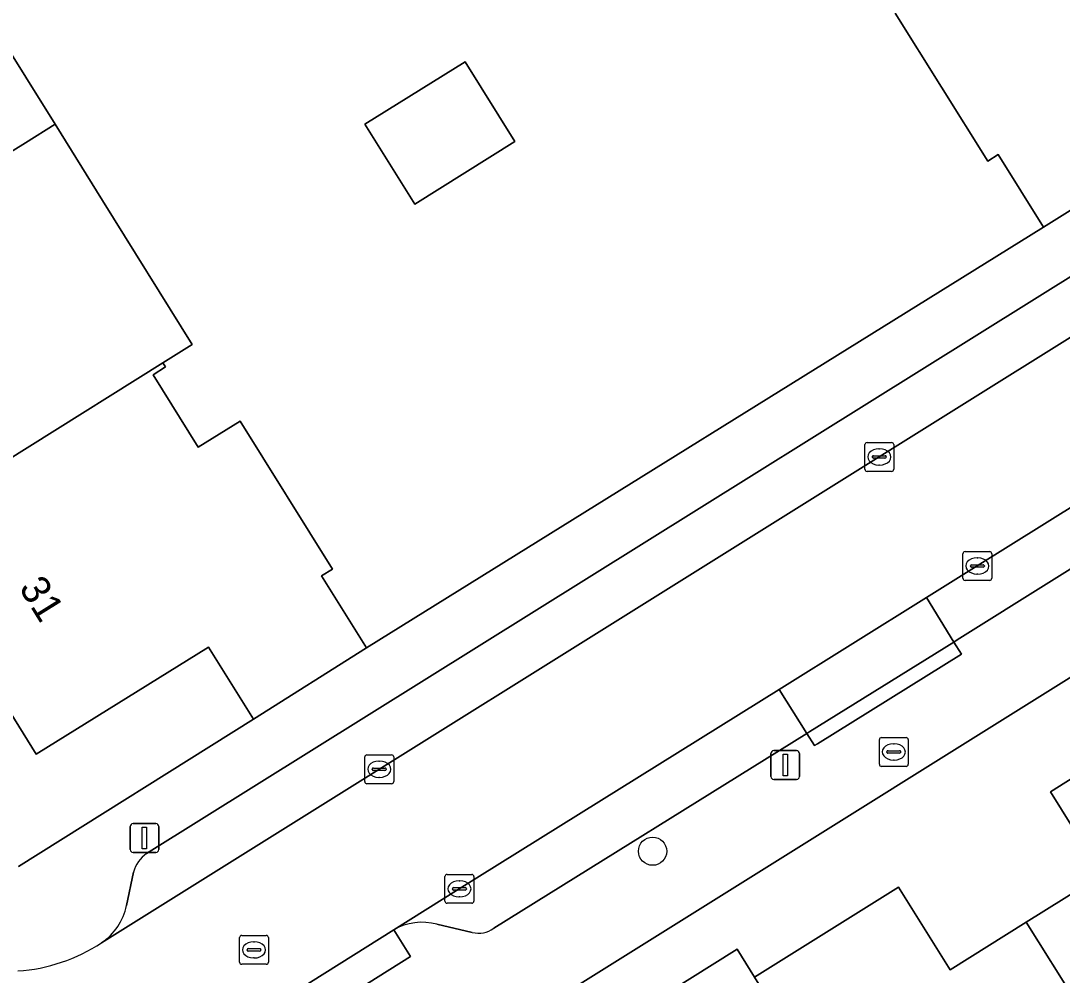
# Model space of a CAD drawing. Extents: x 158835 to 160077, y 386387 to 387778.
# Drawn here: x 159128.32 to 159164.41, y 386936.5 to 386969.57 of the extents above; entities that cross this region are included whole.
import ezdxf

# ---------------------------------------------------------------- set-up
doc = ezdxf.new("R2010")
doc.units = 0
for name, color, linetype in [('IMGEO_Boom', 7, 'Continuous'), ('IMGEO_Brandkraan', 7, 'Continuous'), ('IMGEO_Erf', 7, 'Continuous'), ('IMGEO_Kolk', 7, 'Continuous'), ('IMGEO_Lichtmast', 7, 'Continuous'), ('IMGEO_Muur', 7, 'Continuous'), ('IMGEO_Pand', 7, 'Continuous'), ('IMGEO_Pand_nummerreeks', 7, 'Continuous'), ('IMGEO_Parkeervlak_open', 7, 'Continuous'), ('IMGEO_Rijbaan_lokaal_gesloten', 7, 'Continuous'), ('IMGEO_Rioolput', 7, 'Continuous'), ('IMGEO_Voetpad_open', 7, 'Continuous')]:
    doc.layers.add(name, color=color, linetype=linetype)

msp = doc.modelspace()

# ---------------------------------------------------------------- linework, layer by layer
at = {"layer": 'IMGEO_Boom'}
msp.add_circle((159150.211, 386940.794), 0.489, dxfattribs=at)
at = {"layer": 'IMGEO_Brandkraan'}
for p, q in [((159158.07, 386943.808), (159158.07, 386944.66)), ((159158.145, 386944.734), (159158.997, 386944.734)), ((159158.558, 386944.514), (159158.583, 386944.514)), ((159159.071, 386944.66), (159159.071, 386943.808)), ((159158.329, 386944.228), (159158.329, 386944.24)), ((159158.767, 386944.191), (159158.369, 386944.191)), ((159158.372, 386944.277), (159158.77, 386944.277)), ((159158.813, 386944.24), (159158.813, 386944.228)), ((159158.997, 386943.734), (159158.145, 386943.734)), ((159158.581, 386943.954), (159158.556, 386943.954))]:
    msp.add_line(p, q, dxfattribs=at)
for points in [[(159158.07, 386943.808), (159158.07, 386944.66)], [(159158.145, 386944.734), (159158.997, 386944.734)], [(159159.071, 386944.66), (159159.071, 386943.808)], [(159158.997, 386943.734), (159158.145, 386943.734)]]:
    msp.add_lwpolyline(points, dxfattribs=at)
for centre, radius, start, end in [((159158.147, 386944.658), 0.0765, 91.552, 178.448), ((159158.147, 386944.658), 0.0765, 91.552, 178.448), ((159158.995, 386944.658), 0.0765, 1.552, 88.448), ((159158.995, 386944.658), 0.0765, 1.552, 88.448), ((159158.369, 386944.237), 0.0403, 85.8775, 175.7526), ((159158.366, 386944.227), 0.0366, 178.938, 274.7102), ((159158.77, 386944.234), 0.043, 264.8664, 352.4533), ((159158.774, 386944.239), 0.0386, 1.7309, 96.639), ((159158.147, 386943.81), 0.0765, 181.552, 268.448), ((159158.147, 386943.81), 0.0765, 181.552, 268.448), ((159158.995, 386943.81), 0.0765, 271.552, 358.448), ((159158.995, 386943.81), 0.0765, 271.552, 358.448)]:
    msp.add_arc(centre, radius, start, end, dxfattribs=at)
for centre, major_axis, ratio, start_param, end_param in [((159158.557, 386944.234), (-0.387, 0.002), 0.722429, 4.712389, 7.853982), ((159158.582, 386944.234), (-0.39, 0.002), 0.717154, 1.570796, 4.712389)]:
    msp.add_ellipse(centre, major_axis=major_axis, ratio=ratio, start_param=start_param, end_param=end_param, dxfattribs=at)
at = {"layer": 'IMGEO_Erf'}
for points in [[(159218.693, 386980.571), (159146.59, 386935.503)], [(159126.388, 386970.975), (159129.502, 386965.983), (159131.152, 386963.338), (159134.261, 386958.353), (159133.243, 386957.719), (159133.333, 386957.575), (159132.901, 386957.305), (159134.466, 386954.796), (159135.915, 386955.7), (159139.114, 386950.571), (159138.741, 386950.339), (159140.301, 386947.838), (159163.761, 386962.422), (159162.19, 386964.939), (159161.825, 386964.711), (159158.624, 386969.839)], [(159149.953, 386935.401), (159153.141, 386937.398), (159153.743, 386936.431), (159158.73, 386939.548), (159160.521, 386936.682), (159163.157, 386938.33), (159165.794, 386939.978), (159163.997, 386942.852), (159165.82, 386943.991), (159165.221, 386944.949), (159168.408, 386946.941), (159169.005, 386945.982), (159174, 386949.104), (159175.791, 386946.239), (159178.419, 386947.882), (159181.056, 386949.53), (159179.265, 386952.395), (159184.255, 386955.514), (159183.658, 386956.474), (159186.829, 386958.456), (159187.428, 386957.498), (159189.234, 386958.626), (159191.03, 386955.753), (159193.667, 386957.401)], [(159128.234, 386940.266), (159136.383, 386945.364), (159134.825, 386947.869), (159128.849, 386944.162), (159125.646, 386949.307)]]:
    msp.add_lwpolyline(points, dxfattribs=at)
msp.add_lwpolyline([(159140.242, 386965.987), (159143.715, 386968.153), (159145.443, 386965.383), (159141.97, 386963.217)], close=True, dxfattribs=at)
at = {"layer": 'IMGEO_Kolk'}
for p, q in [((159157.643, 386954.956), (159158.495, 386954.956)), ((159157.568, 386954.03), (159157.568, 386954.882)), ((159158.056, 386954.736), (159158.081, 386954.736)), ((159158.569, 386954.882), (159158.569, 386954.03)), ((159157.827, 386954.45), (159157.827, 386954.462)), ((159158.265, 386954.413), (159157.867, 386954.413)), ((159157.87, 386954.499), (159158.268, 386954.499)), ((159158.311, 386954.462), (159158.311, 386954.45)), ((159158.495, 386953.956), (159157.643, 386953.956)), ((159158.079, 386954.176), (159158.054, 386954.176)), ((159160.967, 386950.251), (159160.967, 386951.103)), ((159161.042, 386951.177), (159161.894, 386951.177)), ((159161.455, 386950.957), (159161.48, 386950.957)), ((159161.968, 386951.103), (159161.968, 386950.251)), ((159161.226, 386950.671), (159161.226, 386950.683)), ((159161.664, 386950.634), (159161.266, 386950.634)), ((159161.269, 386950.72), (159161.667, 386950.72)), ((159161.71, 386950.683), (159161.71, 386950.671)), ((159161.478, 386950.397), (159161.453, 386950.397)), ((159161.894, 386950.177), (159161.042, 386950.177)), ((159140.313, 386944.133), (159141.165, 386944.133)), ((159140.238, 386943.207), (159140.238, 386944.059)), ((159140.726, 386943.913), (159140.751, 386943.913)), ((159141.239, 386944.059), (159141.239, 386943.207)), ((159140.497, 386943.627), (159140.497, 386943.639)), ((159140.935, 386943.59), (159140.537, 386943.59)), ((159140.54, 386943.676), (159140.938, 386943.676)), ((159140.981, 386943.639), (159140.981, 386943.627)), ((159141.165, 386943.133), (159140.313, 386943.133)), ((159140.749, 386943.353), (159140.724, 386943.353)), ((159143.017, 386939.064), (159143.017, 386939.916)), ((159143.092, 386939.99), (159143.944, 386939.99)), ((159143.505, 386939.77), (159143.53, 386939.77)), ((159144.018, 386939.916), (159144.018, 386939.064)), ((159143.276, 386939.484), (159143.276, 386939.496)), ((159143.714, 386939.447), (159143.316, 386939.447)), ((159143.319, 386939.533), (159143.717, 386939.533)), ((159143.76, 386939.496), (159143.76, 386939.484)), ((159143.528, 386939.21), (159143.503, 386939.21)), ((159143.944, 386938.99), (159143.092, 386938.99))]:
    msp.add_line(p, q, dxfattribs=at)
for points in [[(159157.643, 386954.956), (159158.495, 386954.956)], [(159157.568, 386954.03), (159157.568, 386954.882)], [(159158.569, 386954.882), (159158.569, 386954.03)], [(159158.495, 386953.956), (159157.643, 386953.956)], [(159160.967, 386950.251), (159160.967, 386951.103)], [(159161.042, 386951.177), (159161.894, 386951.177)], [(159161.968, 386951.103), (159161.968, 386950.251)], [(159161.894, 386950.177), (159161.042, 386950.177)], [(159140.313, 386944.133), (159141.165, 386944.133)], [(159140.238, 386943.207), (159140.238, 386944.059)], [(159141.239, 386944.059), (159141.239, 386943.207)], [(159141.165, 386943.133), (159140.313, 386943.133)], [(159143.017, 386939.064), (159143.017, 386939.916)], [(159143.092, 386939.99), (159143.944, 386939.99)], [(159144.018, 386939.916), (159144.018, 386939.064)], [(159143.944, 386938.99), (159143.092, 386938.99)]]:
    msp.add_lwpolyline(points, dxfattribs=at)
for centre, radius, start, end in [((159157.645, 386954.88), 0.0765, 91.552, 178.448), ((159157.645, 386954.88), 0.0765, 91.552, 178.448), ((159158.493, 386954.88), 0.0765, 1.552, 88.448), ((159158.493, 386954.88), 0.0765, 1.552, 88.448), ((159157.867, 386954.459), 0.0403, 85.8775, 175.7526), ((159157.864, 386954.449), 0.0366, 178.938, 274.7102), ((159158.268, 386954.456), 0.043, 264.8664, 352.4533), ((159158.272, 386954.461), 0.0386, 1.7309, 96.639), ((159157.645, 386954.032), 0.0765, 181.552, 268.448), ((159157.645, 386954.032), 0.0765, 181.552, 268.448), ((159158.493, 386954.032), 0.0765, 271.552, 358.448), ((159158.493, 386954.032), 0.0765, 271.552, 358.448), ((159161.044, 386951.101), 0.0765, 91.552, 178.448), ((159161.044, 386951.101), 0.0765, 91.552, 178.448), ((159161.892, 386951.101), 0.0765, 1.552, 88.448), ((159161.892, 386951.101), 0.0765, 1.552, 88.448), ((159161.266, 386950.68), 0.0403, 85.8775, 175.7526), ((159161.263, 386950.67), 0.0366, 178.938, 274.7102), ((159161.667, 386950.677), 0.043, 264.8664, 352.4533), ((159161.671, 386950.682), 0.0386, 1.7309, 96.639), ((159161.044, 386950.253), 0.0765, 181.552, 268.448), ((159161.044, 386950.253), 0.0765, 181.552, 268.448), ((159161.892, 386950.253), 0.0765, 271.552, 358.448), ((159161.892, 386950.253), 0.0765, 271.552, 358.448), ((159140.315, 386944.057), 0.0765, 91.552, 178.448), ((159140.315, 386944.057), 0.0765, 91.552, 178.448), ((159141.163, 386944.057), 0.0765, 1.552, 88.448), ((159141.163, 386944.057), 0.0765, 1.552, 88.448), ((159140.537, 386943.636), 0.0403, 85.8775, 175.7526), ((159140.534, 386943.626), 0.0366, 178.938, 274.7102), ((159140.938, 386943.633), 0.043, 264.8664, 352.4533), ((159140.942, 386943.638), 0.0386, 1.7309, 96.639), ((159140.315, 386943.209), 0.0765, 181.552, 268.448), ((159140.315, 386943.209), 0.0765, 181.552, 268.448), ((159141.163, 386943.209), 0.0765, 271.552, 358.448), ((159141.163, 386943.209), 0.0765, 271.552, 358.448), ((159143.094, 386939.914), 0.0765, 91.552, 178.448), ((159143.094, 386939.914), 0.0765, 91.552, 178.448), ((159143.942, 386939.914), 0.0765, 1.552, 88.448), ((159143.942, 386939.914), 0.0765, 1.552, 88.448), ((159143.316, 386939.493), 0.0403, 85.8775, 175.7526), ((159143.313, 386939.483), 0.0366, 178.938, 274.7102), ((159143.717, 386939.49), 0.043, 264.8664, 352.4533), ((159143.721, 386939.495), 0.0386, 1.7309, 96.639), ((159143.094, 386939.066), 0.0765, 181.552, 268.448), ((159143.094, 386939.066), 0.0765, 181.552, 268.448), ((159143.942, 386939.066), 0.0765, 271.552, 358.448), ((159143.942, 386939.066), 0.0765, 271.552, 358.448)]:
    msp.add_arc(centre, radius, start, end, dxfattribs=at)
for centre, major_axis, ratio, start_param, end_param in [((159158.055, 386954.456), (-0.387, 0.002), 0.722429, 4.712389, 7.853982), ((159158.08, 386954.456), (-0.39, 0.002), 0.717154, 1.570796, 4.712389), ((159161.454, 386950.677), (-0.387, 0.002), 0.722429, 4.712389, 7.853982), ((159161.479, 386950.677), (-0.39, 0.002), 0.717154, 1.570796, 4.712389), ((159140.725, 386943.633), (-0.387, 0.002), 0.722429, 4.712389, 7.853982), ((159140.75, 386943.633), (-0.39, 0.002), 0.717154, 1.570796, 4.712389), ((159143.504, 386939.49), (-0.387, 0.002), 0.722429, 4.712389, 7.853982), ((159143.529, 386939.49), (-0.39, 0.002), 0.717154, 1.570796, 4.712389)]:
    msp.add_ellipse(centre, major_axis=major_axis, ratio=ratio, start_param=start_param, end_param=end_param, dxfattribs=at)
at = {"layer": 'IMGEO_Lichtmast'}
for p, q in [((159154.312, 386943.38), (159154.312, 386944.18)), ((159154.312, 386944.18), (159154.312, 386943.38)), ((159154.412, 386944.28), (159155.202, 386944.28)), ((159155.202, 386944.28), (159154.412, 386944.28)), ((159155.302, 386944.18), (159155.302, 386943.38)), ((159155.302, 386943.38), (159155.302, 386944.18)), ((159155.202, 386943.28), (159154.412, 386943.28)), ((159154.412, 386943.28), (159155.202, 386943.28)), ((159132.108, 386940.851), (159132.108, 386941.651)), ((159132.108, 386941.651), (159132.108, 386940.851)), ((159132.208, 386941.751), (159132.998, 386941.751)), ((159132.998, 386941.751), (159132.208, 386941.751)), ((159133.098, 386941.651), (159133.098, 386940.851)), ((159133.098, 386940.851), (159133.098, 386941.651)), ((159132.998, 386940.751), (159132.208, 386940.751)), ((159132.208, 386940.751), (159132.998, 386940.751))]:
    msp.add_line(p, q, dxfattribs=at)
for points in [[(159154.732, 386944.155), (159154.882, 386944.155), (159154.882, 386943.405), (159154.732, 386943.405), (159154.732, 386944.155)], [(159132.528, 386941.626), (159132.678, 386941.626), (159132.678, 386940.876), (159132.528, 386940.876), (159132.528, 386941.626)]]:
    msp.add_lwpolyline(points, dxfattribs=at)
for centre, start, end in [((159154.412, 386944.18), 90, 180), ((159154.412, 386944.18), 90, 180), ((159155.202, 386944.18), 0, 90), ((159155.202, 386944.18), 360, 90), ((159154.412, 386943.38), 180, 270), ((159154.412, 386943.38), 180, 270), ((159155.202, 386943.38), 270, 0), ((159155.202, 386943.38), 270, 0), ((159132.208, 386941.651), 90, 180), ((159132.208, 386941.651), 90, 180), ((159132.998, 386941.651), 0, 90), ((159132.998, 386941.651), 360, 90), ((159132.208, 386940.851), 180, 270), ((159132.208, 386940.851), 180, 270), ((159132.998, 386940.851), 270, 0), ((159132.998, 386940.851), 270, 0)]:
    msp.add_arc(centre, 0.1, start, end, dxfattribs=at)
at = {"layer": 'IMGEO_Muur'}
msp.add_lwpolyline([(159140.301, 386947.838), (159163.761, 386962.422)], dxfattribs=at)
at = {"layer": 'IMGEO_Pand'}
for points in [[(159167.663, 386964.86), (159166.089, 386967.372), (159172.044, 386971.102), (159168.862, 386976.227), (159167.591, 386975.434), (159166.027, 386977.941), (159167.297, 386978.734), (159167.213, 386978.869), (159158.003, 386973.115), (159158.088, 386972.979), (159158.521, 386973.249), (159160.082, 386970.749), (159158.624, 386969.839), (159161.825, 386964.711), (159162.19, 386964.939), (159163.761, 386962.422)], [(159114.488, 386967.227), (159114.573, 386967.091), (159115.848, 386967.884), (159117.408, 386965.377), (159116.133, 386964.584), (159119.237, 386959.595), (159128.476, 386965.343), (159129.502, 386965.983), (159126.388, 386970.975), (159124.938, 386970.071), (159123.373, 386972.58), (159123.805, 386972.85), (159123.72, 386972.986)], [(159140.242, 386965.987), (159141.97, 386963.217), (159145.443, 386965.383), (159143.715, 386968.153)], [(159131.152, 386963.338), (159129.502, 386965.983), (159128.476, 386965.343), (159119.237, 386959.595), (159119.322, 386959.459), (159120.597, 386960.252), (159122.162, 386957.736), (159120.887, 386956.943), (159124.005, 386951.946), (159133.243, 386957.719), (159134.261, 386958.353)], [(159140.301, 386947.838), (159138.741, 386950.339), (159139.114, 386950.571), (159135.915, 386955.7), (159134.466, 386954.796), (159132.901, 386957.305), (159133.333, 386957.575), (159133.243, 386957.719), (159124.005, 386951.946), (159124.09, 386951.81), (159125.358, 386952.599), (159126.914, 386950.096), (159125.646, 386949.307), (159128.849, 386944.162), (159134.825, 386947.869), (159136.383, 386945.364)], [(159169.005, 386945.982), (159168.408, 386946.941), (159165.221, 386944.949), (159165.82, 386943.991), (159163.997, 386942.852), (159165.794, 386939.978), (159163.157, 386938.33), (159166.699, 386932.701), (159167.806, 386930.905), (159170.516, 386932.597), (159169.167, 386934.748), (159174.079, 386937.828)], [(159163.157, 386938.33), (159160.521, 386936.682), (159158.73, 386939.548), (159153.743, 386936.431), (159158.818, 386928.282), (159160.652, 386925.33), (159165.652, 386928.445), (159164.039, 386931.062), (159166.699, 386932.701)], [(159153.743, 386936.431), (159153.141, 386937.398), (159149.953, 386935.401), (159150.548, 386934.442), (159148.75, 386933.325), (159153.814, 386925.173), (159158.818, 386928.282)]]:
    msp.add_lwpolyline(points, close=True, dxfattribs=at)
at = {"layer": 'IMGEO_Parkeervlak_open'}
for points in [[(159131.114, 386937.622), (159158.066, 386954.455), (159177.5, 386966.596), (159180.429, 386968.39)], [(159176.792, 386968.248), (159132.671, 386940.711)], [(159155.557, 386944.875), (159154.604, 386946.403), (159143.513, 386939.491), (159141.241, 386938.069)], [(159144.705, 386938.124), (159155.557, 386944.875)], [(159132.227, 386940.072), (159131.981, 386938.913)], [(159142.739, 386938.261), (159143.964, 386937.981)]]:
    msp.add_lwpolyline(points, dxfattribs=at)
for points in [[(159170.756, 386954.373), (159169.809, 386955.89), (159161.463, 386950.678), (159159.702, 386949.581), (159160.657, 386948.043), (159160.771, 386948.114)], [(159160.657, 386948.043), (159159.702, 386949.581), (159154.604, 386946.403), (159155.557, 386944.875), (159155.66, 386944.939)]]:
    msp.add_lwpolyline(points, close=True, dxfattribs=at)
for centre, radius, start, end in [((159133.281, 386939.813), 1.085, 124.1999, 166.2142), ((159129.952, 386939.339), 2.074, 304.0938, 348.1377), ((159142.22, 386936.37), 1.961, 74.6587, 119.9489), ((159144.184, 386938.832), 0.879, 255.5004, 306.3452)]:
    msp.add_arc(centre, radius, start, end, dxfattribs=at)
at = {"layer": 'IMGEO_Rijbaan_lokaal_gesloten'}
for points in [[(159210.053, 386986.917), (159191.361, 386975.238), (159188.942, 386973.711), (159180.429, 386968.39), (159177.5, 386966.596), (159158.066, 386954.455), (159131.114, 386937.622)], [(159141.241, 386938.069), (159143.513, 386939.491), (159154.604, 386946.403), (159159.702, 386949.581), (159161.463, 386950.678), (159169.809, 386955.89), (159174.889, 386959.062), (159180.293, 386962.436), (159185.031, 386965.399), (159190.218, 386968.642), (159194.491, 386971.313)], [(159129.269, 386930.514), (159132.67, 386932.684), (159141.241, 386938.069)]]:
    msp.add_lwpolyline(points, dxfattribs=at)
msp.add_arc((159127.814, 386942.619), 5.988, 273.8633, 303.4451, dxfattribs=at)
at = {"layer": 'IMGEO_Rioolput'}
for p, q in [((159135.897, 386936.949), (159135.897, 386937.801)), ((159135.972, 386937.875), (159136.824, 386937.875)), ((159136.385, 386937.655), (159136.41, 386937.655)), ((159136.898, 386937.801), (159136.898, 386936.949)), ((159136.156, 386937.369), (159136.156, 386937.381)), ((159136.594, 386937.332), (159136.196, 386937.332)), ((159136.199, 386937.418), (159136.597, 386937.418)), ((159136.64, 386937.381), (159136.64, 386937.369)), ((159136.824, 386936.875), (159135.972, 386936.875)), ((159136.408, 386937.095), (159136.383, 386937.095))]:
    msp.add_line(p, q, dxfattribs=at)
for points in [[(159135.897, 386936.949), (159135.897, 386937.801)], [(159135.972, 386937.875), (159136.824, 386937.875)], [(159136.898, 386937.801), (159136.898, 386936.949)], [(159136.824, 386936.875), (159135.972, 386936.875)]]:
    msp.add_lwpolyline(points, dxfattribs=at)
for centre, radius, start, end in [((159135.974, 386937.799), 0.0765, 91.552, 178.448), ((159135.974, 386937.799), 0.0765, 91.552, 178.448), ((159136.822, 386937.799), 0.0765, 1.552, 88.448), ((159136.822, 386937.799), 0.0765, 1.552, 88.448), ((159136.196, 386937.378), 0.0403, 85.8775, 175.7526), ((159136.193, 386937.368), 0.0366, 178.938, 274.7102), ((159136.597, 386937.375), 0.043, 264.8664, 352.4533), ((159136.601, 386937.38), 0.0386, 1.7309, 96.639), ((159135.974, 386936.951), 0.0765, 181.552, 268.448), ((159135.974, 386936.951), 0.0765, 181.552, 268.448), ((159136.822, 386936.951), 0.0765, 271.552, 358.448), ((159136.822, 386936.951), 0.0765, 271.552, 358.448)]:
    msp.add_arc(centre, radius, start, end, dxfattribs=at)
for centre, major_axis, ratio, start_param, end_param in [((159136.384, 386937.375), (-0.387, 0.002), 0.722429, 4.712389, 7.853982), ((159136.409, 386937.375), (-0.39, 0.002), 0.717154, 1.570796, 4.712389)]:
    msp.add_ellipse(centre, major_axis=major_axis, ratio=ratio, start_param=start_param, end_param=end_param, dxfattribs=at)
at = {"layer": 'IMGEO_Voetpad_open'}
for points in [[(159215.379, 386994.706), (159188.722, 386978.002), (159187.569, 386977.271), (159187.401, 386977.166), (159185.077, 386975.712), (159184.906, 386975.691), (159180.615, 386973.009), (159175.852, 386969.977), (159175.771, 386969.935), (159167.663, 386964.86), (159163.761, 386962.422), (159140.301, 386947.838), (159136.383, 386945.364), (159128.234, 386940.266)], [(159141.241, 386938.069), (159141.821, 386937.146), (159135.408, 386933.117), (159137.51, 386929.772), (159141.766, 386932.423), (159146.59, 386935.503), (159218.693, 386980.571)], [(159201.286, 386973.442), (159191.24, 386967.162), (159191.168, 386967.117), (159191.433, 386966.694), (159186.385, 386963.549), (159186.243, 386963.46), (159185.978, 386963.884), (159175.962, 386957.621), (159175.837, 386957.543), (159176.101, 386957.119), (159171.02, 386953.95), (159170.756, 386954.373), (159160.771, 386948.114), (159160.657, 386948.043), (159160.921, 386947.62), (159155.923, 386944.515), (159155.821, 386944.452), (159155.557, 386944.875), (159144.705, 386938.124)], [(159132.671, 386940.711), (159176.792, 386968.248)], [(159131.981, 386938.913), (159132.227, 386940.072)], [(159143.964, 386937.981), (159142.739, 386938.261)]]:
    msp.add_lwpolyline(points, dxfattribs=at)
for points in [[(159160.921, 386947.62), (159160.657, 386948.043), (159155.66, 386944.939), (159155.557, 386944.875), (159155.821, 386944.452), (159155.923, 386944.515)], [(159141.821, 386937.146), (159141.241, 386938.069), (159132.67, 386932.684), (159133.25, 386931.761), (159135.408, 386933.117)]]:
    msp.add_lwpolyline(points, close=True, dxfattribs=at)
for centre, radius, start, end in [((159133.281, 386939.813), 1.085, 124.1999, 166.2142), ((159129.952, 386939.339), 2.074, 304.0938, 348.1377), ((159142.22, 386936.37), 1.961, 74.6587, 119.9489), ((159144.184, 386938.832), 0.879, 255.5004, 306.3452), ((159127.814, 386942.619), 5.988, 273.8633, 303.4451)]:
    msp.add_arc(centre, radius, start, end, dxfattribs=at)

# ---------------------------------------------------------------- texts
at = {"layer": 'IMGEO_Pand_nummerreeks'}
msp.add_text('31', height=1, rotation=301.9214, dxfattribs=at).set_placement((159128.231, 386949.919))

doc.saveas('drawing.dxf')
